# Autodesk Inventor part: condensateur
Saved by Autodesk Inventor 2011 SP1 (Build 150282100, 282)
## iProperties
Created: 2010-12
Part Number: condensateur
Document SubType Name: Modeling
Designer: eric
Density: 1 g/cm^3
Author: eric
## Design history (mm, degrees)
feature "Base1"
node "Solide1"
node "Corps solides"
node "Corps surfaciques"
